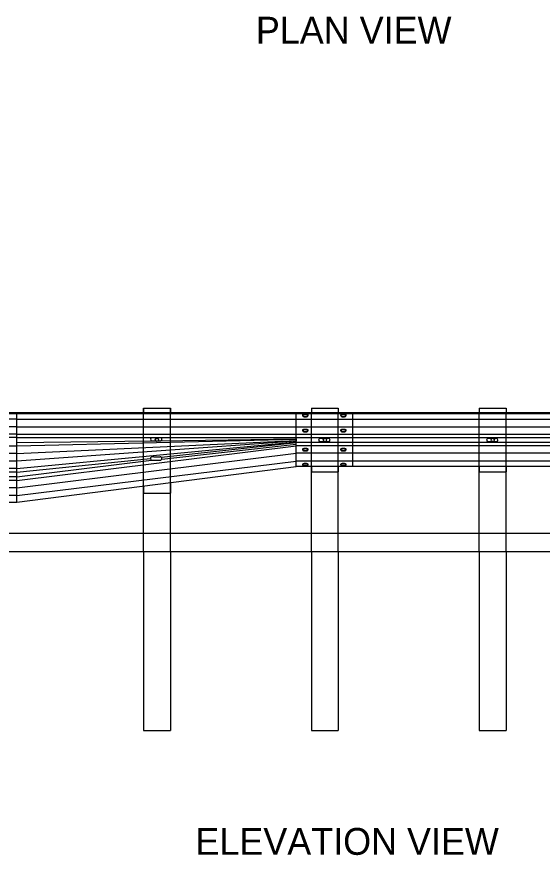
# Model space of a CAD drawing. Extents: x 49991 to 50160, y 49948 to 50051.
# Drawn here: x 50058.22 to 50068, y 50002.88 to 50018.48 of the extents above; entities that cross this region are included whole.
import ezdxf

# ---------------------------------------------------------------- set-up
doc = ezdxf.new("R2010")
doc.units = 0
for name, color, linetype in [('Level 1', 7, 'Continuous'), ('Level 3', 7, 'Continuous'), ('Level 4', 7, 'Continuous')]:
    doc.layers.add(name, color=color, linetype=linetype)

msp = doc.modelspace()

# ---------------------------------------------------------------- linework, layer by layer
at = {"layer": 'Level 1'}
for p, q in [((50057.402, 50011.119), (50093.827, 50011.117)), ((50060.577, 50011.202), (50060.577, 50011.119)), ((50060.577, 50011.202), (50061.077, 50011.202)), ((50060.577, 50011.119), (50060.577, 50011.202)), ((50060.577, 50011.202), (50061.077, 50011.202)), ((50061.077, 50011.202), (50061.077, 50011.119)), ((50061.077, 50011.119), (50061.077, 50011.202)), ((50063.418, 50010.115), (50063.418, 50011.119)), ((50063.702, 50011.202), (50063.702, 50011.119)), ((50063.702, 50011.202), (50064.202, 50011.202)), ((50063.702, 50011.202), (50064.202, 50011.202)), ((50063.702, 50011.202), (50063.702, 50011.119)), ((50064.202, 50011.202), (50064.202, 50011.119)), ((50064.202, 50011.202), (50064.202, 50011.119)), ((50066.827, 50011.202), (50066.827, 50011.119)), ((50066.827, 50011.202), (50067.327, 50011.202)), ((50066.827, 50011.202), (50066.827, 50011.119)), ((50066.827, 50011.202), (50067.327, 50011.202)), ((50067.327, 50011.202), (50067.327, 50011.119)), ((50067.327, 50011.202), (50067.327, 50011.119)), ((50058.217, 50010.998), (50039.473, 50010.998)), ((50057.402, 50011.099), (50093.827, 50011.097)), ((50058.217, 50010.998), (50093.827, 50010.998)), ((50063.539, 50011.069), (50063.539, 50011.062)), ((50063.578, 50011.091), (50063.598, 50011.091)), ((50063.578, 50011.084), (50063.578, 50011.091)), ((50063.598, 50011.084), (50063.578, 50011.084)), ((50063.598, 50011.047), (50063.578, 50011.047)), ((50063.578, 50011.04), (50063.578, 50011.047)), ((50063.578, 50011.04), (50063.598, 50011.04)), ((50063.598, 50011.084), (50063.598, 50011.091)), ((50063.598, 50011.04), (50063.598, 50011.047)), ((50063.637, 50011.062), (50063.637, 50011.069)), ((50064.248, 50011.069), (50064.248, 50011.062)), ((50064.287, 50011.084), (50064.287, 50011.091)), ((50064.287, 50011.091), (50064.307, 50011.091)), ((50064.307, 50011.084), (50064.287, 50011.084)), ((50064.307, 50011.047), (50064.287, 50011.047)), ((50064.287, 50011.04), (50064.287, 50011.047)), ((50064.287, 50011.04), (50064.307, 50011.04)), ((50064.307, 50011.084), (50064.307, 50011.091)), ((50064.307, 50011.04), (50064.307, 50011.047)), ((50064.346, 50011.062), (50064.346, 50011.069)), ((50058.217, 50010.852), (50039.473, 50010.852)), ((50058.217, 50010.852), (50093.827, 50010.849)), ((50063.578, 50010.811), (50063.598, 50010.811)), ((50063.578, 50010.811), (50063.578, 50010.803)), ((50063.598, 50010.811), (50063.598, 50010.803)), ((50064.287, 50010.811), (50064.307, 50010.811)), ((50064.287, 50010.811), (50064.287, 50010.803)), ((50064.307, 50010.811), (50064.307, 50010.803)), ((50058.217, 50010.717), (50039.473, 50010.717)), ((50058.217, 50010.652), (50052.524, 50010.651)), ((50058.217, 50010.717), (50093.827, 50010.722)), ((50058.217, 50010.652), (50060.722, 50010.653)), ((50060.738, 50010.656), (50060.885, 50010.656)), ((50060.896, 50010.655), (50093.827, 50010.643)), ((50063.539, 50010.788), (50063.539, 50010.781)), ((50063.598, 50010.803), (50063.578, 50010.803)), ((50063.578, 50010.766), (50063.578, 50010.759)), ((50063.598, 50010.766), (50063.578, 50010.766)), ((50063.578, 50010.759), (50063.598, 50010.759)), ((50063.598, 50010.766), (50063.598, 50010.759)), ((50063.637, 50010.781), (50063.637, 50010.788)), ((50064.248, 50010.788), (50064.248, 50010.781)), ((50064.307, 50010.803), (50064.287, 50010.803)), ((50064.287, 50010.766), (50064.287, 50010.759)), ((50064.307, 50010.766), (50064.287, 50010.766)), ((50064.287, 50010.759), (50064.307, 50010.759)), ((50064.307, 50010.766), (50064.307, 50010.759)), ((50064.346, 50010.781), (50064.346, 50010.788)), ((50058.219, 50010.494), (50039.473, 50010.494)), ((50063.418, 50010.615), (50058.217, 50010.494)), ((50058.217, 50010.359), (50063.418, 50010.601)), ((50058.217, 50010.559), (50060.73, 50010.591)), ((50063.418, 50010.585), (50058.217, 50010.213)), ((50058.217, 50010.078), (50063.418, 50010.571)), ((50058.217, 50009.855), (50063.418, 50010.496)), ((50060.738, 50010.591), (50060.885, 50010.591)), ((50060.885, 50010.591), (50063.418, 50010.627)), ((50060.911, 50010.287), (50063.418, 50010.558)), ((50060.915, 50010.253), (50063.418, 50010.532)), ((50063.418, 50010.63), (50063.418, 50010.621)), ((50063.418, 50010.621), (50063.418, 50010.611)), ((50063.418, 50010.611), (50063.418, 50010.602)), ((50063.418, 50010.602), (50063.418, 50010.593)), ((50063.418, 50010.593), (50063.418, 50010.584)), ((50093.827, 50010.56), (50063.418, 50010.561)), ((50093.827, 50010.496), (50063.418, 50010.496)), ((50063.869, 50010.64), (50064.016, 50010.64)), ((50064.016, 50010.574), (50063.869, 50010.574)), ((50066.994, 50010.639), (50067.141, 50010.639)), ((50067.141, 50010.574), (50066.994, 50010.574)), ((50058.221, 50010.359), (50039.473, 50010.359)), ((50058.217, 50009.72), (50063.418, 50010.361)), ((50093.827, 50010.362), (50063.418, 50010.361)), ((50063.539, 50010.432), (50063.539, 50010.425)), ((50063.578, 50010.454), (50063.598, 50010.454)), ((50063.578, 50010.447), (50063.578, 50010.454)), ((50063.598, 50010.447), (50063.578, 50010.447)), ((50063.598, 50010.41), (50063.578, 50010.41)), ((50063.578, 50010.403), (50063.578, 50010.41)), ((50063.578, 50010.403), (50063.598, 50010.403)), ((50063.598, 50010.447), (50063.598, 50010.454)), ((50063.598, 50010.403), (50063.598, 50010.41)), ((50063.637, 50010.425), (50063.637, 50010.432)), ((50064.248, 50010.432), (50064.248, 50010.425)), ((50064.287, 50010.454), (50064.307, 50010.454)), ((50064.287, 50010.447), (50064.287, 50010.454)), ((50064.307, 50010.447), (50064.287, 50010.447)), ((50064.307, 50010.41), (50064.287, 50010.41)), ((50064.287, 50010.403), (50064.287, 50010.41)), ((50064.287, 50010.403), (50064.307, 50010.403)), ((50064.307, 50010.447), (50064.307, 50010.454)), ((50064.307, 50010.403), (50064.307, 50010.41)), ((50064.346, 50010.425), (50064.346, 50010.432)), ((50058.217, 50010.213), (50039.473, 50010.213)), ((50058.217, 50010.012), (50060.705, 50010.264)), ((50058.217, 50009.92), (50060.726, 50010.232)), ((50058.217, 50009.574), (50063.418, 50010.216)), ((50060.726, 50010.232), (50060.738, 50010.23)), ((50060.771, 50010.296), (50060.738, 50010.296)), ((50060.738, 50010.23), (50060.885, 50010.23)), ((50060.771, 50010.296), (50060.885, 50010.296)), ((50093.827, 50010.216), (50063.418, 50010.216)), ((50058.217, 50010.078), (50039.473, 50010.078)), ((50058.217, 50009.452), (50063.418, 50010.115)), ((50093.827, 50010.115), (50063.418, 50010.115)), ((50063.539, 50010.152), (50063.539, 50010.145)), ((50063.578, 50010.174), (50063.598, 50010.174)), ((50063.578, 50010.174), (50063.578, 50010.167)), ((50063.598, 50010.167), (50063.578, 50010.167)), ((50063.578, 50010.13), (50063.578, 50010.123)), ((50063.598, 50010.13), (50063.578, 50010.13)), ((50063.578, 50010.123), (50063.598, 50010.123)), ((50063.598, 50010.174), (50063.598, 50010.167)), ((50063.598, 50010.13), (50063.598, 50010.123)), ((50063.637, 50010.145), (50063.637, 50010.152)), ((50063.702, 50008.868), (50063.702, 50010.115)), ((50063.702, 50010.115), (50063.702, 50010.015)), ((50064.202, 50008.868), (50064.202, 50010.115)), ((50064.202, 50010.115), (50064.202, 50010.015)), ((50064.248, 50010.152), (50064.248, 50010.145)), ((50064.287, 50010.174), (50064.307, 50010.174)), ((50064.287, 50010.174), (50064.287, 50010.167)), ((50064.307, 50010.167), (50064.287, 50010.167)), ((50064.287, 50010.13), (50064.287, 50010.123)), ((50064.307, 50010.13), (50064.287, 50010.13)), ((50064.287, 50010.123), (50064.307, 50010.123)), ((50064.307, 50010.174), (50064.307, 50010.167)), ((50064.307, 50010.13), (50064.307, 50010.123)), ((50064.346, 50010.145), (50064.346, 50010.152)), ((50066.827, 50008.868), (50066.827, 50010.115)), ((50066.827, 50010.115), (50066.827, 50010.014)), ((50067.327, 50008.868), (50067.327, 50010.115)), ((50067.327, 50010.115), (50067.327, 50010.014)), ((50058.217, 50009.92), (50052.51, 50009.92)), ((50058.217, 50010.012), (50052.527, 50010.012)), ((50063.702, 50010.015), (50064.202, 50010.015)), ((50066.827, 50010.014), (50067.327, 50010.014)), ((50058.217, 50009.855), (50039.473, 50009.855)), ((50058.217, 50009.72), (50039.473, 50009.72)), ((50060.577, 50008.868), (50060.577, 50009.753)), ((50060.577, 50009.753), (50060.577, 50009.619)), ((50061.077, 50008.868), (50061.077, 50009.817)), ((50061.077, 50009.817), (50061.077, 50009.619)), ((50058.217, 50009.574), (50039.473, 50009.574)), ((50060.577, 50009.619), (50061.077, 50009.619)), ((50038.232, 50009.452), (50058.217, 50009.452)), ((50093.827, 50008.867), (50039.473, 50008.869)), ((50034.505, 50008.536), (50093.827, 50008.534))]:
    msp.add_line(p, q, dxfattribs=at)
for points in [[(50063.578, 50011.047), (50063.571, 50011.047), (50063.565, 50011.048), (50063.559, 50011.05), (50063.553, 50011.052), (50063.548, 50011.055), (50063.544, 50011.058), (50063.541, 50011.061), (50063.54, 50011.065), (50063.539, 50011.069), (50063.54, 50011.073), (50063.541, 50011.076), (50063.544, 50011.08), (50063.548, 50011.083), (50063.553, 50011.086), (50063.559, 50011.088), (50063.565, 50011.09), (50063.571, 50011.091), (50063.578, 50011.091)], [(50063.578, 50011.084), (50063.571, 50011.083), (50063.565, 50011.082), (50063.559, 50011.081), (50063.553, 50011.079), (50063.548, 50011.076), (50063.544, 50011.073), (50063.541, 50011.069), (50063.54, 50011.065), (50063.539, 50011.065)], [(50063.539, 50011.065), (50063.539, 50011.062), (50063.54, 50011.058), (50063.541, 50011.054), (50063.544, 50011.051), (50063.548, 50011.047), (50063.553, 50011.045), (50063.559, 50011.043), (50063.565, 50011.041), (50063.571, 50011.04), (50063.578, 50011.04)], [(50063.598, 50011.091), (50063.605, 50011.091), (50063.611, 50011.09), (50063.618, 50011.088), (50063.623, 50011.086), (50063.628, 50011.083), (50063.632, 50011.08), (50063.635, 50011.076), (50063.637, 50011.073), (50063.637, 50011.069), (50063.637, 50011.065), (50063.635, 50011.061), (50063.632, 50011.058), (50063.628, 50011.055), (50063.623, 50011.052), (50063.618, 50011.05), (50063.611, 50011.048), (50063.605, 50011.047), (50063.598, 50011.047)], [(50063.637, 50011.065), (50063.637, 50011.065), (50063.635, 50011.069), (50063.632, 50011.073), (50063.628, 50011.076), (50063.623, 50011.079), (50063.618, 50011.081), (50063.611, 50011.082), (50063.605, 50011.083), (50063.598, 50011.084)], [(50063.598, 50011.04), (50063.605, 50011.04), (50063.611, 50011.041), (50063.618, 50011.043), (50063.623, 50011.045), (50063.628, 50011.047), (50063.632, 50011.051), (50063.635, 50011.054), (50063.637, 50011.058), (50063.637, 50011.062), (50063.637, 50011.065)], [(50064.287, 50011.047), (50064.28, 50011.047), (50064.273, 50011.048), (50064.267, 50011.05), (50064.262, 50011.052), (50064.257, 50011.055), (50064.253, 50011.058), (50064.25, 50011.061), (50064.248, 50011.065), (50064.248, 50011.069), (50064.248, 50011.073), (50064.25, 50011.076), (50064.253, 50011.08), (50064.257, 50011.083), (50064.262, 50011.086), (50064.267, 50011.088), (50064.273, 50011.09), (50064.28, 50011.091), (50064.287, 50011.091)], [(50064.287, 50011.084), (50064.28, 50011.083), (50064.273, 50011.082), (50064.267, 50011.081), (50064.262, 50011.079), (50064.257, 50011.076), (50064.253, 50011.073), (50064.25, 50011.069), (50064.248, 50011.065), (50064.248, 50011.065)], [(50064.248, 50011.065), (50064.248, 50011.062), (50064.248, 50011.058), (50064.25, 50011.054), (50064.253, 50011.051), (50064.257, 50011.047), (50064.262, 50011.045), (50064.267, 50011.043), (50064.273, 50011.041), (50064.28, 50011.04), (50064.287, 50011.04)], [(50064.307, 50011.091), (50064.313, 50011.091), (50064.32, 50011.09), (50064.326, 50011.088), (50064.332, 50011.086), (50064.337, 50011.083), (50064.341, 50011.08), (50064.344, 50011.076), (50064.345, 50011.073), (50064.346, 50011.069), (50064.345, 50011.065), (50064.344, 50011.061), (50064.341, 50011.058), (50064.337, 50011.055), (50064.332, 50011.052), (50064.326, 50011.05), (50064.32, 50011.048), (50064.313, 50011.047), (50064.307, 50011.047)], [(50064.345, 50011.065), (50064.345, 50011.065), (50064.344, 50011.069), (50064.341, 50011.073), (50064.337, 50011.076), (50064.332, 50011.079), (50064.326, 50011.081), (50064.32, 50011.082), (50064.313, 50011.083), (50064.307, 50011.084)], [(50064.307, 50011.04), (50064.313, 50011.04), (50064.32, 50011.041), (50064.326, 50011.043), (50064.332, 50011.045), (50064.337, 50011.047), (50064.341, 50011.051), (50064.344, 50011.054), (50064.345, 50011.058), (50064.346, 50011.062), (50064.345, 50011.065)], [(50063.539, 50010.785), (50063.539, 50010.788), (50063.54, 50010.792), (50063.541, 50010.796), (50063.544, 50010.8), (50063.548, 50010.803), (50063.553, 50010.805), (50063.559, 50010.808), (50063.565, 50010.809), (50063.571, 50010.81), (50063.578, 50010.811)], [(50063.598, 50010.811), (50063.605, 50010.81), (50063.611, 50010.809), (50063.618, 50010.808), (50063.623, 50010.805), (50063.628, 50010.803), (50063.632, 50010.8), (50063.635, 50010.796), (50063.637, 50010.792), (50063.637, 50010.788), (50063.637, 50010.785)], [(50064.248, 50010.785), (50064.248, 50010.788), (50064.248, 50010.792), (50064.25, 50010.796), (50064.253, 50010.8), (50064.257, 50010.803), (50064.262, 50010.805), (50064.267, 50010.808), (50064.273, 50010.809), (50064.28, 50010.81), (50064.287, 50010.811)], [(50064.307, 50010.811), (50064.313, 50010.81), (50064.32, 50010.809), (50064.326, 50010.808), (50064.332, 50010.805), (50064.337, 50010.803), (50064.341, 50010.8), (50064.344, 50010.796), (50064.345, 50010.792), (50064.346, 50010.788), (50064.345, 50010.785)], [(50060.723, 50010.653), (50060.733, 50010.656), (50060.738, 50010.656)], [(50060.885, 50010.656), (50060.896, 50010.655), (50060.9, 50010.653)], [(50063.578, 50010.803), (50063.571, 50010.803), (50063.565, 50010.802), (50063.559, 50010.8), (50063.553, 50010.798), (50063.548, 50010.795), (50063.544, 50010.792), (50063.541, 50010.789), (50063.54, 50010.785), (50063.539, 50010.781), (50063.54, 50010.777), (50063.541, 50010.774), (50063.544, 50010.77), (50063.548, 50010.767), (50063.553, 50010.764), (50063.559, 50010.762), (50063.565, 50010.761), (50063.571, 50010.76), (50063.578, 50010.759)], [(50063.578, 50010.766), (50063.571, 50010.767), (50063.565, 50010.768), (50063.559, 50010.769), (50063.553, 50010.772), (50063.548, 50010.774), (50063.544, 50010.777), (50063.541, 50010.781), (50063.54, 50010.785), (50063.539, 50010.785)], [(50063.598, 50010.759), (50063.605, 50010.76), (50063.611, 50010.761), (50063.618, 50010.762), (50063.623, 50010.764), (50063.628, 50010.767), (50063.632, 50010.77), (50063.635, 50010.774), (50063.637, 50010.777), (50063.637, 50010.781), (50063.637, 50010.785), (50063.635, 50010.789), (50063.632, 50010.792), (50063.628, 50010.795), (50063.623, 50010.798), (50063.618, 50010.8), (50063.611, 50010.802), (50063.605, 50010.803), (50063.598, 50010.803)], [(50063.637, 50010.785), (50063.637, 50010.785), (50063.635, 50010.781), (50063.632, 50010.777), (50063.628, 50010.774), (50063.623, 50010.772), (50063.618, 50010.769), (50063.611, 50010.768), (50063.605, 50010.767), (50063.598, 50010.766)], [(50064.287, 50010.803), (50064.28, 50010.803), (50064.273, 50010.802), (50064.267, 50010.8), (50064.262, 50010.798), (50064.257, 50010.795), (50064.253, 50010.792), (50064.25, 50010.789), (50064.248, 50010.785), (50064.248, 50010.781), (50064.248, 50010.777), (50064.25, 50010.774), (50064.253, 50010.77), (50064.257, 50010.767), (50064.262, 50010.764), (50064.267, 50010.762), (50064.273, 50010.761), (50064.28, 50010.76), (50064.287, 50010.759)], [(50064.287, 50010.766), (50064.28, 50010.767), (50064.273, 50010.768), (50064.267, 50010.769), (50064.262, 50010.772), (50064.257, 50010.774), (50064.253, 50010.777), (50064.25, 50010.781), (50064.248, 50010.785), (50064.248, 50010.785)], [(50064.307, 50010.759), (50064.313, 50010.76), (50064.32, 50010.761), (50064.326, 50010.762), (50064.332, 50010.764), (50064.337, 50010.767), (50064.341, 50010.77), (50064.344, 50010.774), (50064.345, 50010.777), (50064.346, 50010.781), (50064.345, 50010.785), (50064.344, 50010.789), (50064.341, 50010.792), (50064.337, 50010.795), (50064.332, 50010.798), (50064.326, 50010.8), (50064.32, 50010.802), (50064.313, 50010.803), (50064.307, 50010.803)], [(50064.345, 50010.785), (50064.345, 50010.785), (50064.344, 50010.781), (50064.341, 50010.777), (50064.337, 50010.774), (50064.332, 50010.772), (50064.326, 50010.769), (50064.32, 50010.768), (50064.313, 50010.767), (50064.307, 50010.766)], [(50060.723, 50010.594), (50060.734, 50010.591), (50060.738, 50010.591)], [(50060.885, 50010.591), (50060.896, 50010.593), (50060.904, 50010.597)], [(50063.578, 50010.41), (50063.571, 50010.411), (50063.565, 50010.412), (50063.559, 50010.413), (50063.553, 50010.416), (50063.548, 50010.418), (50063.544, 50010.421), (50063.541, 50010.425), (50063.54, 50010.429), (50063.539, 50010.432), (50063.54, 50010.436), (50063.541, 50010.44), (50063.544, 50010.443), (50063.548, 50010.447), (50063.553, 50010.449), (50063.559, 50010.452), (50063.565, 50010.453), (50063.571, 50010.454), (50063.578, 50010.454)], [(50063.578, 50010.447), (50063.571, 50010.447), (50063.565, 50010.446), (50063.559, 50010.444), (50063.553, 50010.442), (50063.548, 50010.439), (50063.544, 50010.436), (50063.541, 50010.433), (50063.54, 50010.429), (50063.539, 50010.429)], [(50063.539, 50010.429), (50063.539, 50010.425), (50063.54, 50010.421), (50063.541, 50010.418), (50063.544, 50010.414), (50063.548, 50010.411), (50063.553, 50010.408), (50063.559, 50010.406), (50063.565, 50010.404), (50063.571, 50010.403), (50063.578, 50010.403)], [(50063.598, 50010.454), (50063.605, 50010.454), (50063.611, 50010.453), (50063.618, 50010.452), (50063.623, 50010.449), (50063.628, 50010.447), (50063.632, 50010.443), (50063.635, 50010.44), (50063.637, 50010.436), (50063.637, 50010.432), (50063.637, 50010.429), (50063.635, 50010.425), (50063.632, 50010.421), (50063.628, 50010.418), (50063.623, 50010.416), (50063.618, 50010.413), (50063.611, 50010.412), (50063.605, 50010.411), (50063.598, 50010.41)], [(50063.637, 50010.429), (50063.637, 50010.429), (50063.635, 50010.433), (50063.632, 50010.436), (50063.628, 50010.439), (50063.623, 50010.442), (50063.618, 50010.444), (50063.611, 50010.446), (50063.605, 50010.447), (50063.598, 50010.447)], [(50063.598, 50010.403), (50063.605, 50010.403), (50063.611, 50010.404), (50063.618, 50010.406), (50063.623, 50010.408), (50063.628, 50010.411), (50063.632, 50010.414), (50063.635, 50010.418), (50063.637, 50010.421), (50063.637, 50010.425), (50063.637, 50010.429)], [(50064.287, 50010.41), (50064.28, 50010.411), (50064.273, 50010.412), (50064.267, 50010.413), (50064.262, 50010.416), (50064.257, 50010.418), (50064.253, 50010.421), (50064.25, 50010.425), (50064.248, 50010.429), (50064.248, 50010.432), (50064.248, 50010.436), (50064.25, 50010.44), (50064.253, 50010.443), (50064.257, 50010.447), (50064.262, 50010.449), (50064.267, 50010.452), (50064.273, 50010.453), (50064.28, 50010.454), (50064.287, 50010.454)], [(50064.287, 50010.447), (50064.28, 50010.447), (50064.273, 50010.446), (50064.267, 50010.444), (50064.262, 50010.442), (50064.257, 50010.439), (50064.253, 50010.436), (50064.25, 50010.433), (50064.248, 50010.429), (50064.248, 50010.429)], [(50064.248, 50010.429), (50064.248, 50010.425), (50064.248, 50010.421), (50064.25, 50010.418), (50064.253, 50010.414), (50064.257, 50010.411), (50064.262, 50010.408), (50064.267, 50010.406), (50064.273, 50010.404), (50064.28, 50010.403), (50064.287, 50010.403)], [(50064.307, 50010.454), (50064.313, 50010.454), (50064.32, 50010.453), (50064.326, 50010.452), (50064.332, 50010.449), (50064.337, 50010.447), (50064.341, 50010.443), (50064.344, 50010.44), (50064.345, 50010.436), (50064.346, 50010.432), (50064.345, 50010.429), (50064.344, 50010.425), (50064.341, 50010.421), (50064.337, 50010.418), (50064.332, 50010.416), (50064.326, 50010.413), (50064.32, 50010.412), (50064.313, 50010.411), (50064.307, 50010.41)], [(50064.345, 50010.429), (50064.345, 50010.429), (50064.344, 50010.433), (50064.341, 50010.436), (50064.337, 50010.439), (50064.332, 50010.442), (50064.326, 50010.444), (50064.32, 50010.446), (50064.313, 50010.447), (50064.307, 50010.447)], [(50064.307, 50010.403), (50064.313, 50010.403), (50064.32, 50010.404), (50064.326, 50010.406), (50064.332, 50010.408), (50064.337, 50010.411), (50064.341, 50010.414), (50064.344, 50010.418), (50064.345, 50010.421), (50064.346, 50010.425), (50064.345, 50010.429)], [(50060.738, 50010.296), (50060.727, 50010.294), (50060.719, 50010.29)], [(50060.885, 50010.23), (50060.896, 50010.232), (50060.905, 50010.237), (50060.913, 50010.245), (50060.915, 50010.25), (50060.917, 50010.256)], [(50063.539, 50010.148), (50063.539, 50010.152), (50063.54, 50010.156), (50063.541, 50010.16), (50063.544, 50010.163), (50063.548, 50010.166), (50063.553, 50010.169), (50063.559, 50010.171), (50063.565, 50010.173), (50063.571, 50010.174), (50063.578, 50010.174)], [(50063.578, 50010.167), (50063.571, 50010.166), (50063.565, 50010.165), (50063.559, 50010.164), (50063.553, 50010.162), (50063.548, 50010.159), (50063.544, 50010.156), (50063.541, 50010.152), (50063.54, 50010.149), (50063.539, 50010.145), (50063.54, 50010.141), (50063.541, 50010.137), (50063.544, 50010.134), (50063.548, 50010.131), (50063.553, 50010.128), (50063.559, 50010.126), (50063.565, 50010.124), (50063.571, 50010.123), (50063.578, 50010.123)], [(50063.578, 50010.13), (50063.571, 50010.13), (50063.565, 50010.131), (50063.559, 50010.133), (50063.553, 50010.135), (50063.548, 50010.138), (50063.544, 50010.141), (50063.541, 50010.144), (50063.54, 50010.148), (50063.539, 50010.148)], [(50063.598, 50010.174), (50063.605, 50010.174), (50063.611, 50010.173), (50063.618, 50010.171), (50063.623, 50010.169), (50063.628, 50010.166), (50063.632, 50010.163), (50063.635, 50010.16), (50063.637, 50010.156), (50063.637, 50010.152), (50063.637, 50010.148)], [(50063.598, 50010.123), (50063.605, 50010.123), (50063.611, 50010.124), (50063.618, 50010.126), (50063.623, 50010.128), (50063.628, 50010.131), (50063.632, 50010.134), (50063.635, 50010.137), (50063.637, 50010.141), (50063.637, 50010.145), (50063.637, 50010.149), (50063.635, 50010.152), (50063.632, 50010.156), (50063.628, 50010.159), (50063.623, 50010.162), (50063.618, 50010.164), (50063.611, 50010.165), (50063.605, 50010.166), (50063.598, 50010.167)], [(50063.637, 50010.148), (50063.637, 50010.148), (50063.635, 50010.144), (50063.632, 50010.141), (50063.628, 50010.138), (50063.623, 50010.135), (50063.618, 50010.133), (50063.611, 50010.131), (50063.605, 50010.13), (50063.598, 50010.13)], [(50064.248, 50010.148), (50064.248, 50010.152), (50064.248, 50010.156), (50064.25, 50010.16), (50064.253, 50010.163), (50064.257, 50010.166), (50064.262, 50010.169), (50064.267, 50010.171), (50064.273, 50010.173), (50064.28, 50010.174), (50064.287, 50010.174)], [(50064.287, 50010.167), (50064.28, 50010.166), (50064.273, 50010.165), (50064.267, 50010.164), (50064.262, 50010.162), (50064.257, 50010.159), (50064.253, 50010.156), (50064.25, 50010.152), (50064.248, 50010.149), (50064.248, 50010.145), (50064.248, 50010.141), (50064.25, 50010.137), (50064.253, 50010.134), (50064.257, 50010.131), (50064.262, 50010.128), (50064.267, 50010.126), (50064.273, 50010.124), (50064.28, 50010.123), (50064.287, 50010.123)], [(50064.287, 50010.13), (50064.28, 50010.13), (50064.273, 50010.131), (50064.267, 50010.133), (50064.262, 50010.135), (50064.257, 50010.138), (50064.253, 50010.141), (50064.25, 50010.144), (50064.248, 50010.148), (50064.248, 50010.148)], [(50064.307, 50010.174), (50064.313, 50010.174), (50064.32, 50010.173), (50064.326, 50010.171), (50064.332, 50010.169), (50064.337, 50010.166), (50064.341, 50010.163), (50064.344, 50010.16), (50064.345, 50010.156), (50064.346, 50010.152), (50064.345, 50010.148)], [(50064.307, 50010.123), (50064.313, 50010.123), (50064.32, 50010.124), (50064.326, 50010.126), (50064.332, 50010.128), (50064.337, 50010.131), (50064.341, 50010.134), (50064.344, 50010.137), (50064.345, 50010.141), (50064.346, 50010.145), (50064.345, 50010.149), (50064.344, 50010.152), (50064.341, 50010.156), (50064.337, 50010.159), (50064.332, 50010.162), (50064.326, 50010.164), (50064.32, 50010.165), (50064.313, 50010.166), (50064.307, 50010.167)], [(50064.345, 50010.148), (50064.345, 50010.148), (50064.344, 50010.144), (50064.341, 50010.141), (50064.337, 50010.138), (50064.332, 50010.135), (50064.326, 50010.133), (50064.32, 50010.131), (50064.313, 50010.13), (50064.307, 50010.13)]]:
    msp.add_lwpolyline(points, dxfattribs=at)
for centre in [(50060.827, 50010.608), (50063.952, 50010.608), (50067.077, 50010.608)]:
    msp.add_circle(centre, 0.0312, dxfattribs=at)
for centre, start, end in [((50060.738, 50010.624), 117.1386, 243.6106), ((50060.885, 50010.624), 304.6387, 62.8614), ((50063.869, 50010.607), 90, 270), ((50064.016, 50010.607), 270, 90), ((50066.994, 50010.607), 90, 270), ((50067.141, 50010.607), 270, 90), ((50060.738, 50010.263), 124.0204, 249.0228), ((50060.885, 50010.263), 347.308, 90)]:
    msp.add_arc(centre, 0.0328, start, end, dxfattribs=at)
at = {"layer": 'Level 4'}
for p, q in [((50058.217, 50009.452), (50058.217, 50011.119)), ((50060.577, 50009.766), (50060.577, 50011.119)), ((50060.577, 50009.753), (50060.577, 50011.119)), ((50061.077, 50009.817), (50061.077, 50011.119)), ((50061.077, 50009.817), (50061.077, 50011.119)), ((50063.702, 50010.115), (50063.702, 50011.119)), ((50063.702, 50010.115), (50063.702, 50011.119)), ((50064.202, 50010.115), (50064.202, 50011.119)), ((50064.202, 50010.115), (50064.202, 50011.119)), ((50064.467, 50011.119), (50064.467, 50011.104)), ((50066.827, 50010.115), (50066.827, 50011.119)), ((50066.827, 50010.115), (50066.827, 50011.119)), ((50067.327, 50010.115), (50067.327, 50011.119)), ((50067.327, 50010.115), (50067.327, 50011.119)), ((50064.467, 50011.104), (50064.467, 50011.098)), ((50064.467, 50011.098), (50064.467, 50010.998)), ((50064.467, 50010.998), (50064.467, 50010.853)), ((50064.467, 50010.853), (50064.467, 50010.718)), ((50064.467, 50010.718), (50064.467, 50010.653)), ((50064.467, 50010.653), (50064.467, 50010.561)), ((50064.467, 50010.561), (50064.467, 50010.496)), ((50064.467, 50010.496), (50064.467, 50010.361)), ((50064.467, 50010.361), (50064.467, 50010.216)), ((50064.467, 50010.216), (50064.467, 50010.115)), ((50060.577, 50008.535), (50060.577, 50008.868)), ((50061.077, 50008.535), (50061.077, 50008.868)), ((50063.702, 50008.535), (50063.702, 50008.868)), ((50064.202, 50008.535), (50064.202, 50008.868)), ((50066.827, 50008.535), (50066.827, 50008.868)), ((50067.327, 50008.535), (50067.327, 50008.868)), ((50060.577, 50008.536), (50060.577, 50005.202)), ((50061.077, 50008.536), (50061.077, 50005.202)), ((50063.702, 50008.535), (50063.702, 50005.202)), ((50064.202, 50008.535), (50064.202, 50005.202)), ((50066.827, 50008.535), (50066.827, 50005.202)), ((50067.327, 50008.535), (50067.327, 50005.202)), ((50060.577, 50005.202), (50061.077, 50005.202)), ((50063.702, 50005.202), (50064.202, 50005.202)), ((50066.827, 50005.202), (50067.327, 50005.202))]:
    msp.add_line(p, q, dxfattribs=at)

# ---------------------------------------------------------------- texts
at = {"layer": 'Level 3'}
for s, p in [('PLAN VIEW', (50062.668, 50017.981)), ('ELEVATION VIEW', (50061.543, 50002.89))]:
    msp.add_text(s, height=0.5, dxfattribs=at).set_placement(p)

doc.saveas('drawing.dxf')
